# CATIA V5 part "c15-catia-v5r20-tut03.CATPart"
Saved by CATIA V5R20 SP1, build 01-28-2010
Part number: Part1
Bounding box of the stored display mesh (mm): x -75 to 75, y -40 to 40, z 0 to 5
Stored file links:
  D:\v5_r20\psrt_files_downloaded\c15-catia-v5r20-prt\c15-catia-v5r20-tut03.CATPart
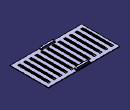
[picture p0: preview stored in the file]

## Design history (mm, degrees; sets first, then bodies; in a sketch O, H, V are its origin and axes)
SheetMetalParameters1: Thickness 1, BendRadius 2, KFactor 0.400515 {= log(min(100,max(20*SheetMetalParameters1.BendRadius,SheetMetalParameters1.Thickness)/SheetMetalParameters1.Thickness))/log(100)/2}, ReliefRadialLength 1, ReliefAxialLength 2, MinimumBendRadius 0
Body1 (main body)
  Sketch1 on xy-plane, origin (0, 0, 0), H (1, 0, 0), V (0, 1, 0)
    line L1 (75, 40) -> (75, -40)
    line L2 (75, -40) -> (-75, -40)
    line L3 (-75, -40) -> (-75, 40)
    line L4 (-75, 40) -> (75, 40)
    length L4 = 150
    length L1 = 80
    vertical: L1 V, L3 V
    horizontal: L2 H, L4 H
    equidistance: L1 L3 O, L2 L4 O
  Wall1: Thickness 1, Profile Sketch1
  Sketch2 on face of Wall1, origin (0, 0, 0), H (1, 0, 0), V (0, 1, 0)
    line L1 (64.5, 30) -> (67, 30)
    line L2 (67, 30) -> (67, -30)
    line L3 (67, -30) -> (64.5, -30)
    line L4 (64.5, -30) -> (64.5, 30)
    reference projected line E1 (75, 40) -> (75, -40) from edge [face of Wall1 | face of Wall1]
    reference projected line E2 (-75, 40) -> (75, 40) from edge [face of Wall1 | face of Wall1]
    length L2 = 60
    distance L2 L4 = 2.5
    distance E1 L2 = 8
    distance L1 E2 = 10
    horizontal: L1 H, L3 H
    vertical: L2 V, L4 V
  d_Stamp1: NewRoot_AttribNormalisation "No Standard", Stamp_FilletRadius 2
  RectPattern1: of d_Stamp1, direction 1 instances 12, spacing 12, along face of Wall1 reversed
  Sketch3 on face of Wall1, origin (0, 0, 0), H (1, 0, 0), V (0, -1, 0)
    point P1 (0, 36.5)
    reference projected line E1 (75, 40) -> (75, -40) from edge [face of Wall1 | face of Wall1]
    reference projected line E2 (-75, 40) -> (75, 40) from edge [face of Wall1 | face of Wall1]
    distance P1 E1 = 75
    distance P1 E2 = 3.5
  Sketch4 on face of Wall1, origin (0, -36.5, 0), H (1, 0, 0), V (0, 1, 0)
    point P1 (0, 0)
    reference projected point E1 (0, 0) from Sketch3.P1
    coincidence: E1 P1
  d_Stamp2: NewRoot_AttribNormalisation "No Standard", Stamp_FilletRadius 0.5
  SHM_Mirror1: MirroringPlane zx-plane, ObjectToMirror d_Stamp2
